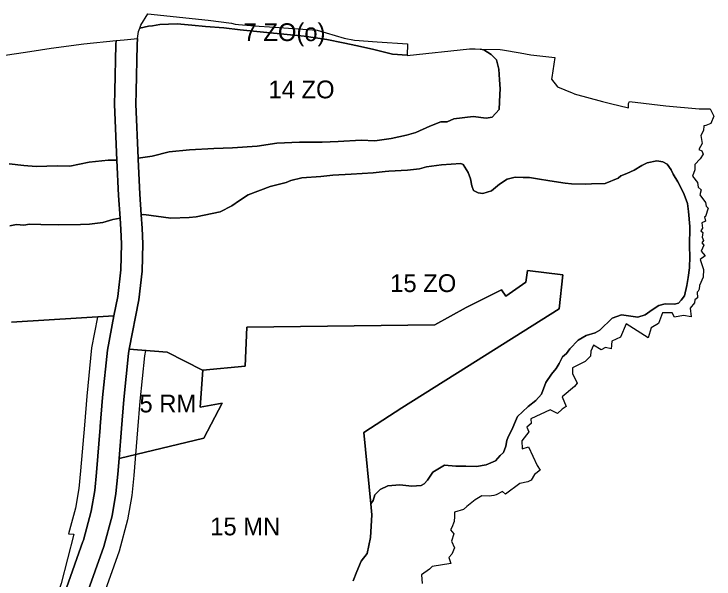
# Model space of a CAD drawing. Extents: x 7418056 to 7420315, y 5537846 to 5539505.
# Drawn here: x 7419814.6 to 7420208.4, y 5538568.2 to 5538886.1 of the extents above; entities that cross this region are included whole.
import ezdxf

# ---------------------------------------------------------------- set-up
doc = ezdxf.new("R2010")
doc.units = 0
for name, color, linetype in [('linie_rozgraniczajace', 7, 'Continuous'), ('linie_zabudowy_nieprzekraczalne', 7, 'Continuous'), ('oznaczenia_przeznaczen', 7, 'Continuous')]:
    doc.layers.add(name, color=color, linetype=linetype)

msp = doc.modelspace()

# ---------------------------------------------------------------- linework, layer by layer
at = {"layer": 'linie_rozgraniczajace'}
for points in [[(7419885.38, 5538878.14), (7419885.94, 5538879.78), (7419889.79, 5538886.1), (7419923.8, 5538882.66), (7419936.92, 5538880.94), (7419939.02, 5538880.34), (7419940.89, 5538880.24), (7419952.48, 5538879.31), (7419958.29, 5538878.91), (7419985.15, 5538877.05), (7420000.33, 5538872.55), (7420006.21, 5538871.43), (7420018.81, 5538870.42), (7420035.92, 5538869.29), (7420035.76, 5538862.78), (7420035.77, 5538862.97), (7420027.55, 5538863.58), (7420017.05, 5538866.11), (7420007.78, 5538868.25), (7419999.8, 5538869.94), (7419990.53, 5538871.83), (7419977.77, 5538873.64), (7419956.82, 5538875.78), (7419941.89, 5538877.11), (7419932.57, 5538878.25), (7419922.4, 5538879.12), (7419914.62, 5538879.88), (7419906.39, 5538880.63), (7419896.71, 5538880.23), (7419892.43, 5538879.41), (7419890.28, 5538879.32)], [(7419883.14, 5538835.3), (7419883.28, 5538842.4), (7419883.95, 5538868.68), (7419884.02, 5538872.39), (7419884.71, 5538876.16), (7419885.38, 5538878.14), (7419890.28, 5538879.32), (7419892.43, 5538879.41), (7419896.71, 5538880.23), (7419906.39, 5538880.63), (7419914.62, 5538879.88), (7419922.4, 5538879.12), (7419932.57, 5538878.25), (7419941.89, 5538877.11), (7419956.82, 5538875.78), (7419977.77, 5538873.64), (7419990.53, 5538871.83), (7419999.8, 5538869.94), (7420007.78, 5538868.25), (7420017.05, 5538866.11), (7420027.55, 5538863.58), (7420035.77, 5538862.97), (7420035.76, 5538862.78), (7420070.76, 5538866.43), (7420074.06, 5538866.45), (7420076.82, 5538866.4), (7420078.88, 5538865.99), (7420083.08, 5538863.36), (7420085.93, 5538860.22), (7420087.29, 5538855.14), (7420087.78, 5538849.09), (7420087.99, 5538843.95), (7420087.88, 5538840.73), (7420087.57, 5538832.32), (7420083.65, 5538828.07), (7420080.22, 5538827.5), (7420072.85, 5538828.49), (7420062.02, 5538827.02), (7420058.35, 5538825.47), (7420054.66, 5538825.38), (7420048.51, 5538822.98), (7420040.59, 5538819.37), (7420035.34, 5538817.92), (7420026.69, 5538816.01), (7420017.63, 5538814.7), (7420009.81, 5538815.16), (7419996.91, 5538814.42), (7419987.86, 5538814.05), (7419975.15, 5538813.96), (7419962.46, 5538813.45), (7419951.32, 5538811.71), (7419937.56, 5538810.72), (7419927.01, 5538810.5), (7419913.24, 5538809.73), (7419901.87, 5538808.62), (7419892.29, 5538806.04), (7419884.45, 5538804.99)], [(7419873.67, 5538635.88), (7419875.08, 5538652.92), (7419876.4, 5538669.12), (7419879, 5538695.12), (7419879.45, 5538697.45), (7419900.68, 5538695.74), (7419920.58, 5538685.6), (7419920.74, 5538685.62), (7419919.28, 5538664.76), (7419931.62, 5538667.1), (7419921.36, 5538647.35)]]:
    msp.add_lwpolyline(points, close=True, dxfattribs=at)
for points in [[(7419844.15, 5538563.23), (7419853.34, 5538589.23), (7419853.62, 5538590.02), (7419857.98, 5538606.25), (7419860.06, 5538617.95), (7419861, 5538628.16), (7419863.07, 5538653.49), (7419863.12, 5538653.88), (7419864.44, 5538670.2), (7419867.11, 5538696.85), (7419870.81, 5538716.16), (7419872.91, 5538727.11), (7419874.69, 5538742.14), (7419875.01, 5538756.69), (7419874.69, 5538764.9), (7419874.22, 5538771.22), (7419873.3, 5538784.02), (7419872.5, 5538803.83), (7419871.14, 5538835.15), (7419871.28, 5538842.67), (7419871.96, 5538868.94), (7419871.99, 5538871.1), (7419876.56, 5538871.58), (7419884.02, 5538872.39), (7419883.95, 5538868.68), (7419883.28, 5538842.4), (7419883.14, 5538835.3), (7419884.45, 5538804.99), (7419884.49, 5538804.34), (7419885.28, 5538784.7), (7419886.12, 5538773.11), (7419886.67, 5538765.58), (7419887.02, 5538756.79), (7419886.68, 5538741.31), (7419884.78, 5538725.27)], [(7419807.13, 5538862.49), (7419823.48, 5538865.05), (7419835.53, 5538866.8), (7419853.95, 5538869.22), (7419871.99, 5538871.1), (7419871.96, 5538868.94), (7419871.28, 5538842.67), (7419871.14, 5538835.15), (7419872.5, 5538803.83), (7419867.6, 5538803.86), (7419856.89, 5538802.73), (7419846, 5538800.41), (7419838.97, 5538800.6), (7419827.06, 5538800.35), (7419820.03, 5538800.76), (7419811.8, 5538801.83)], [(7420115.95, 5538792.17), (7420109.13, 5538793.29), (7420104.66, 5538794.05), (7420101.04, 5538794.03), (7420096.52, 5538794.36), (7420092.04, 5538793.14), (7420087.64, 5538790.36), (7420083.21, 5538786.64), (7420078.36, 5538785.04), (7420075.77, 5538785.4), (7420073.15, 5538786.7), (7420072.11, 5538789.46), (7420071.48, 5538793.41), (7420070.17, 5538796.85), (7420067.18, 5538801.41), (7420065.98, 5538802.06), (7420055.03, 5538801.14), (7420046.66, 5538800.1), (7420042.73, 5538799.01), (7420035.97, 5538798.27), (7420025.5, 5538797.61), (7420023.4, 5538797.53), (7420016.66, 5538796.79), (7420004.29, 5538796.05), (7419994.02, 5538795.4), (7419987.28, 5538794.66), (7419976.55, 5538793.99), (7419970.3, 5538792.34), (7419967.77, 5538791.3), (7419958.74, 5538789.07), (7419946.32, 5538784.35), (7419941.53, 5538781.12), (7419937.21, 5538778.15), (7419930.56, 5538774.83), (7419921.52, 5538772.84), (7419917.12, 5538771.96), (7419913.16, 5538771.56), (7419902.89, 5538771.14), (7419887.68, 5538773.29), (7419886.12, 5538773.11), (7419885.28, 5538784.7), (7419884.49, 5538804.34), (7419884.45, 5538804.99), (7419892.29, 5538806.04), (7419901.87, 5538808.62), (7419913.24, 5538809.73), (7419927.01, 5538810.5), (7419937.56, 5538810.72), (7419951.32, 5538811.71), (7419962.46, 5538813.45), (7419975.15, 5538813.96), (7419987.86, 5538814.05), (7419996.91, 5538814.42), (7420009.81, 5538815.16), (7420017.63, 5538814.7), (7420026.69, 5538816.01), (7420035.34, 5538817.92), (7420040.59, 5538819.37), (7420048.51, 5538822.98), (7420054.66, 5538825.38), (7420058.35, 5538825.47), (7420062.02, 5538827.02), (7420072.85, 5538828.49), (7420080.22, 5538827.5), (7420083.65, 5538828.07), (7420087.57, 5538832.32), (7420087.88, 5538840.73), (7420087.99, 5538843.95), (7420087.78, 5538849.09), (7420087.29, 5538855.14), (7420085.93, 5538860.22), (7420083.08, 5538863.36), (7420078.88, 5538865.99), (7420076.82, 5538866.4), (7420088.15, 5538866.21), (7420089.4, 5538866), (7420099.39, 5538864.25), (7420105.35, 5538863.19), (7420118.78, 5538861.68), (7420117.06, 5538850.33), (7420116.9, 5538849.4), (7420120.34, 5538845.15), (7420128.51, 5538841.71), (7420129.45, 5538841.27), (7420129.66, 5538841.21), (7420145.69, 5538836.94), (7420150.22, 5538835.81), (7420160.36, 5538833.25), (7420160.35, 5538835.64), (7420160.75, 5538836.89), (7420181.3, 5538834.34), (7420199.99, 5538832.75), (7420206.19, 5538832.68), (7420208.38, 5538828.59), (7420206.66, 5538824.43), (7420203.7, 5538823.31), (7420202.75, 5538823.25), (7420202.52, 5538820.52), (7420201.02, 5538817.69), (7420201.76, 5538813.28)], [(7420201.76, 5538813.28), (7420199.79, 5538809.81), (7420201.61, 5538809.01), (7420202.34, 5538807.14), (7420200.68, 5538804.52), (7420197.52, 5538801.35), (7420197.64, 5538798.47), (7420196.35, 5538794.93), (7420199.1, 5538791.36), (7420199.38, 5538788.6), (7420201.08, 5538787.12), (7420200.46, 5538784.29), (7420203.63, 5538780.06), (7420203.9, 5538777.96), (7420205.06, 5538776.79), (7420203.55, 5538772.14), (7420203.09, 5538772.02), (7420203.54, 5538769.58), (7420201.56, 5538768.5), (7420201.96, 5538765.57), (7420201.02, 5538764.07), (7420202.19, 5538763.2), (7420201.75, 5538760.56), (7420202.56, 5538758.7), (7420201.46, 5538757.35), (7420202.58, 5538756.05), (7420201.23, 5538752.57), (7420203.4, 5538750.08), (7420200.54, 5538747.91), (7420202.54, 5538742.24), (7420202.33, 5538738.07), (7420200.24, 5538733.4), (7420200.06, 5538731.26), (7420199.55, 5538730.07), (7420198.98, 5538729.51), (7420199.01, 5538726.45), (7420197.58, 5538725.32), (7420197.37, 5538723.6), (7420194.96, 5538720.56), (7420195.6, 5538715.77), (7420191.25, 5538716.38), (7420186.13, 5538715.47), (7420184.86, 5538717.96), (7420179.36, 5538717.86), (7420177.25, 5538711.93), (7420172.95, 5538709.54), (7420171.4, 5538703.78), (7420158.88, 5538711.67), (7420155.69, 5538704.19), (7420150.83, 5538702.07), (7420150.6, 5538697.65), (7420147.33, 5538698.34), (7420144.88, 5538697.09), (7420140.56, 5538699.73), (7420139.12, 5538696.4), (7420138.98, 5538693.51), (7420135.89, 5538690.62), (7420128.79, 5538686.98), (7420128.84, 5538683.86), (7420131.33, 5538678.4), (7420129.83, 5538676.46), (7420122.94, 5538670.73), (7420125.19, 5538665.26), (7420122.9, 5538663.79), (7420120.38, 5538661.23), (7420116.29, 5538663.27), (7420105.33, 5538658.29), (7420105.47, 5538655.67), (7420103.01, 5538653.58), (7420104.18, 5538651.03), (7420100.18, 5538645.91), (7420100.46, 5538641.47), (7420104.03, 5538642.56), (7420108.94, 5538632.03), (7420110.66, 5538629.36), (7420107.43, 5538626.95), (7420105.52, 5538623.78), (7420103.62, 5538622.84), (7420099.07, 5538621.81), (7420091.15, 5538615.98), (7420089.35, 5538617.47), (7420085.84, 5538615.47), (7420084.6, 5538615.06), (7420081.88, 5538614.77), (7420077.71, 5538615.01), (7420073.98, 5538612.62), (7420069.24, 5538608.93), (7420067.38, 5538607.35), (7420062.46, 5538605.83), (7420062.43, 5538603.32), (7420062.16, 5538600.55), (7420060.92, 5538597.14), (7420060.12, 5538595.85), (7420061.97, 5538593.63), (7420060.77, 5538589.51), (7420062.45, 5538585.7), (7420060.93, 5538582.2), (7420059.24, 5538580.19), (7420060.32, 5538576.95), (7420049.83, 5538575.2)], [(7419811.8, 5538801.83), (7419820.03, 5538800.76), (7419827.06, 5538800.35), (7419838.97, 5538800.6), (7419846, 5538800.41), (7419856.89, 5538802.73), (7419867.6, 5538803.86), (7419872.5, 5538803.83), (7419873.3, 5538784.02), (7419874.22, 5538771.22), (7419870.26, 5538770.48), (7419864.48, 5538768.85), (7419857.04, 5538767.85), (7419851.9, 5538767.64), (7419839.75, 5538767.38), (7419829.69, 5538767.68), (7419823.37, 5538767.88), (7419820.12, 5538767.29), (7419815.9, 5538767.58), (7419812.18, 5538766.97)], [(7419879.45, 5538697.45), (7419884.78, 5538725.27), (7419886.68, 5538741.31), (7419887.02, 5538756.79), (7419886.67, 5538765.58), (7419886.12, 5538773.11), (7419887.68, 5538773.29), (7419902.89, 5538771.14), (7419913.16, 5538771.56), (7419917.12, 5538771.96), (7419921.52, 5538772.84), (7419930.56, 5538774.83), (7419937.21, 5538778.15), (7419941.53, 5538781.12), (7419946.32, 5538784.35), (7419958.74, 5538789.07), (7419967.77, 5538791.3), (7419970.3, 5538792.34), (7419976.55, 5538793.99), (7419987.28, 5538794.66), (7419994.02, 5538795.4), (7420004.29, 5538796.05), (7420016.66, 5538796.79), (7420023.4, 5538797.53), (7420025.5, 5538797.61), (7420035.97, 5538798.27), (7420042.73, 5538799.01), (7420046.66, 5538800.1), (7420055.03, 5538801.14), (7420065.98, 5538802.06), (7420067.18, 5538801.41), (7420070.17, 5538796.85), (7420071.48, 5538793.41), (7420072.11, 5538789.46), (7420073.15, 5538786.7), (7420075.77, 5538785.4), (7420078.36, 5538785.04), (7420083.21, 5538786.64), (7420087.64, 5538790.36), (7420092.04, 5538793.14), (7420096.52, 5538794.36), (7420101.04, 5538794.03), (7420104.66, 5538794.05), (7420109.13, 5538793.29), (7420115.95, 5538792.17), (7420124.66, 5538790.89), (7420128.18, 5538790.56), (7420136.13, 5538790.43), (7420139.39, 5538790.56), (7420147.11, 5538790.63), (7420154.47, 5538793.73), (7420156.06, 5538794.97), (7420159.28, 5538796.27), (7420163.4, 5538798.31), (7420167.74, 5538800.82), (7420170.72, 5538802.34), (7420176.29, 5538803.5), (7420179.58, 5538802.93), (7420181.97, 5538801.62), (7420184.21, 5538798.45), (7420185.47, 5538795.93), (7420187.99, 5538791.59), (7420189.76, 5538788.39), (7420191.54, 5538784.45), (7420193.49, 5538779.49), (7420194.02, 5538775), (7420194.7, 5538766.52), (7420194.61, 5538755.18), (7420194.84, 5538749.59), (7420194.63, 5538743.26), (7420193.91, 5538737.86), (7420193.16, 5538733.39), (7420191.76, 5538727.49), (7420189.99, 5538725.09), (7420188.46, 5538723.29), (7420186.22, 5538722.86), (7420181, 5538722.98), (7420177.38, 5538722.15), (7420173.67, 5538719.56), (7420169.61, 5538716.8), (7420165.49, 5538715.59), (7420156.4, 5538716.78), (7420151.12, 5538714.87), (7420144.11, 5538708.13), (7420141.6, 5538706.62), (7420136.51, 5538705.12), (7420131.92, 5538702.51), (7420127.25, 5538697.62), (7420125.48, 5538694.99), (7420123.09, 5538693.12), (7420121.33, 5538689.4), (7420119.54, 5538686.55), (7420117.05, 5538683.5), (7420113.77, 5538678.67), (7420111.43, 5538672.22), (7420108.08, 5538668.58), (7420103.77, 5538665.14), (7420100.62, 5538662.21), (7420097.84, 5538659.54), (7420096.11, 5538655.73)], [(7420005.33, 5538567.06), (7420007.47, 5538572.46), (7420009.84, 5538578.11), (7420013.31, 5538582.59), (7420015.21, 5538591.53), (7420015.91, 5538604.22), (7420015.3, 5538610.47), (7420016.55, 5538612.34), (7420017.54, 5538615.47), (7420020.55, 5538618.54), (7420024.81, 5538620.63), (7420031.57, 5538621.08), (7420038.37, 5538620.31), (7420043.67, 5538620.74), (7420045.42, 5538621.7), (7420047.12, 5538623.74), (7420049.14, 5538626.67), (7420050.22, 5538628.25), (7420056.84, 5538632.18), (7420063.11, 5538631.73), (7420068.85, 5538631.62), (7420074.81, 5538631.45), (7420080.12, 5538632.38), (7420085.38, 5538634.56), (7420088.13, 5538637.61), (7420089.97, 5538639.25), (7420091.21, 5538642.95), (7420091.8, 5538646.18), (7420092.6, 5538648.12), (7420094.86, 5538652.38), (7420096.11, 5538655.73), (7420097.84, 5538659.54), (7420100.62, 5538662.21), (7420103.77, 5538665.14), (7420108.08, 5538668.58), (7420111.43, 5538672.22), (7420113.77, 5538678.67), (7420117.05, 5538683.5), (7420119.54, 5538686.55), (7420121.33, 5538689.4), (7420123.09, 5538693.12), (7420125.48, 5538694.99), (7420127.25, 5538697.62), (7420131.92, 5538702.51), (7420136.51, 5538705.12), (7420141.6, 5538706.62), (7420144.11, 5538708.13), (7420151.12, 5538714.87), (7420156.4, 5538716.78), (7420165.49, 5538715.59), (7420169.61, 5538716.8), (7420173.67, 5538719.56), (7420177.38, 5538722.15), (7420181, 5538722.98), (7420186.22, 5538722.86), (7420188.46, 5538723.29), (7420189.99, 5538725.09), (7420191.76, 5538727.49), (7420193.16, 5538733.39), (7420193.91, 5538737.86), (7420194.63, 5538743.26), (7420194.84, 5538749.59), (7420194.61, 5538755.18), (7420194.7, 5538766.52), (7420194.02, 5538775), (7420193.49, 5538779.49), (7420191.54, 5538784.45), (7420189.76, 5538788.39), (7420187.99, 5538791.59), (7420185.47, 5538795.93), (7420184.21, 5538798.45), (7420181.97, 5538801.62), (7420179.58, 5538802.93), (7420176.29, 5538803.5), (7420170.72, 5538802.34), (7420167.74, 5538800.82), (7420163.4, 5538798.31), (7420159.28, 5538796.27), (7420156.06, 5538794.97), (7420154.47, 5538793.73), (7420147.11, 5538790.63), (7420139.39, 5538790.56), (7420136.13, 5538790.43), (7420128.18, 5538790.56), (7420124.66, 5538790.89), (7420115.95, 5538792.17)], [(7419812.18, 5538766.97), (7419815.9, 5538767.58), (7419820.12, 5538767.29), (7419823.37, 5538767.88), (7419829.69, 5538767.68), (7419839.75, 5538767.38), (7419851.9, 5538767.64), (7419857.04, 5538767.85), (7419864.48, 5538768.85), (7419870.26, 5538770.48), (7419874.22, 5538771.22), (7419874.69, 5538764.9), (7419875.01, 5538756.69), (7419874.69, 5538742.14), (7419872.91, 5538727.11), (7419870.81, 5538716.16), (7419813.18, 5538712.6)], [(7419855.39, 5538559.04), (7419865.09, 5538586.45), (7419869.73, 5538603.73), (7419871.96, 5538616.35), (7419872.96, 5538627.12), (7419873.67, 5538635.88), (7419921.36, 5538647.35), (7419931.62, 5538667.1), (7419919.28, 5538664.76), (7419920.74, 5538685.62), (7419944.69, 5538688), (7419945.57, 5538709.85), (7420051.26, 5538711.09), (7420069, 5538720.97), (7420088.77, 5538730.95), (7420091.35, 5538727.37), (7420102.58, 5538735.2), (7420103.42, 5538741.75), (7420123.26, 5538739.31), (7420121.19, 5538720.1), (7420069.07, 5538687.44), (7420032.72, 5538664.39), (7420011.44, 5538650.51), (7420015.3, 5538610.47), (7420015.91, 5538604.22), (7420015.21, 5538591.53), (7420013.31, 5538582.59), (7420009.84, 5538578.11), (7420007.47, 5538572.46), (7420005.33, 5538567.06)], [(7420096.11, 5538655.73), (7420094.86, 5538652.38), (7420092.6, 5538648.12), (7420091.8, 5538646.18), (7420091.21, 5538642.95), (7420089.97, 5538639.25), (7420088.13, 5538637.61), (7420085.38, 5538634.56), (7420080.12, 5538632.38), (7420074.81, 5538631.45), (7420068.85, 5538631.62), (7420063.11, 5538631.73), (7420056.84, 5538632.18), (7420050.22, 5538628.25), (7420049.14, 5538626.67), (7420047.12, 5538623.74), (7420045.42, 5538621.7), (7420043.67, 5538620.74), (7420038.37, 5538620.31), (7420031.57, 5538621.08), (7420024.81, 5538620.63), (7420020.55, 5538618.54), (7420017.54, 5538615.47), (7420016.55, 5538612.34), (7420015.3, 5538610.47), (7420011.44, 5538650.51), (7420032.72, 5538664.39), (7420069.07, 5538687.44), (7420121.19, 5538720.1), (7420123.26, 5538739.31), (7420103.42, 5538741.75), (7420102.58, 5538735.2), (7420091.35, 5538727.37), (7420088.77, 5538730.95), (7420069, 5538720.97), (7420051.26, 5538711.09), (7419945.57, 5538709.85), (7419944.69, 5538688), (7419920.74, 5538685.62), (7419920.58, 5538685.6), (7419900.68, 5538695.74), (7419879.45, 5538697.45)], [(7419884.78, 5538725.27), (7419879.45, 5538697.45), (7419879, 5538695.12), (7419876.4, 5538669.12), (7419875.08, 5538652.92), (7419873.67, 5538635.88), (7419872.96, 5538627.12), (7419871.96, 5538616.35), (7419869.73, 5538603.73), (7419865.09, 5538586.45), (7419855.39, 5538559.04)], [(7419813.18, 5538712.6), (7419870.81, 5538716.16), (7419867.11, 5538696.85), (7419864.44, 5538670.2), (7419863.12, 5538653.88), (7419863.07, 5538653.49), (7419861, 5538628.16), (7419860.06, 5538617.95), (7419857.98, 5538606.25), (7419853.62, 5538590.02), (7419853.34, 5538589.23), (7419844.15, 5538563.23), (7419833.74, 5538537.98), (7419821.56, 5538510.24), (7419817.34, 5538500.18), (7419816.12, 5538497.47), (7419809.77, 5538493.53)], [(7420049.83, 5538575.2), (7420048.38, 5538573.6), (7420043.81, 5538570.47), (7420044.19, 5538565.56)]]:
    msp.add_lwpolyline(points, dxfattribs=at)
at = {"layer": 'linie_zabudowy_nieprzekraczalne'}
for points in [[(7419861.54, 5538715.59), (7419858.2, 5538698.16), (7419855.48, 5538671.02), (7419854.16, 5538654.64), (7419852.03, 5538628.95), (7419851.14, 5538619.15), (7419849.17, 5538608.06), (7419845.31, 5538593.55)], [(7419888.47, 5538696.71), (7419887.92, 5538693.83), (7419885.36, 5538668.31), (7419884.06, 5538652.19), (7419881.92, 5538626.35), (7419880.89, 5538615.16), (7419878.48, 5538601.52), (7419873.68, 5538583.78), (7419863.82, 5538555.89), (7419857.54, 5538539.96), (7419840.89, 5538502.02), (7419837.8, 5538494.43), (7419833.83, 5538485.72), (7419832.18, 5538480.95), (7419830.66, 5538475.33), (7419828.18, 5538457.53)], [(7419845.31, 5538593.55), (7419848.17, 5538593.31), (7419841.03, 5538565.71), (7419831.72, 5538538.31), (7419819.7, 5538510.97), (7419816.67, 5538503.53), (7419815.59, 5538501.16), (7419813.55, 5538500.05), (7419801.39, 5538501.82), (7419776.06, 5538503.53), (7419727.84, 5538507.63), (7419679.48, 5538515.57), (7419676.31, 5538521.13)]]:
    msp.add_lwpolyline(points, dxfattribs=at)

# ---------------------------------------------------------------- texts
at = {"layer": 'oznaczenia_przeznaczen'}
for s, p in [('7 ZO(o)', (7419943.73, 5538870.87)), ('14 ZO', (7419957.75, 5538838.65)), ('15 ZO', (7420026.21, 5538729.64)), ('5 RM', (7419885.16, 5538661.89)), ('15 MN', (7419924.96, 5538592.73))]:
    msp.add_text(s, height=10, dxfattribs=at).set_placement(p)

doc.saveas('drawing.dxf')
